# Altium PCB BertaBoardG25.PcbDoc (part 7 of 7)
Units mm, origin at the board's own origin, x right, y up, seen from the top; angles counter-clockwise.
Board outline 160 x 160 mm, 4 copper layers (Top, GND Plane, Power Plane, Bottom), stack 1.344 mm thick; 17 components, 112 nets, 2311 pads, 138 vias.
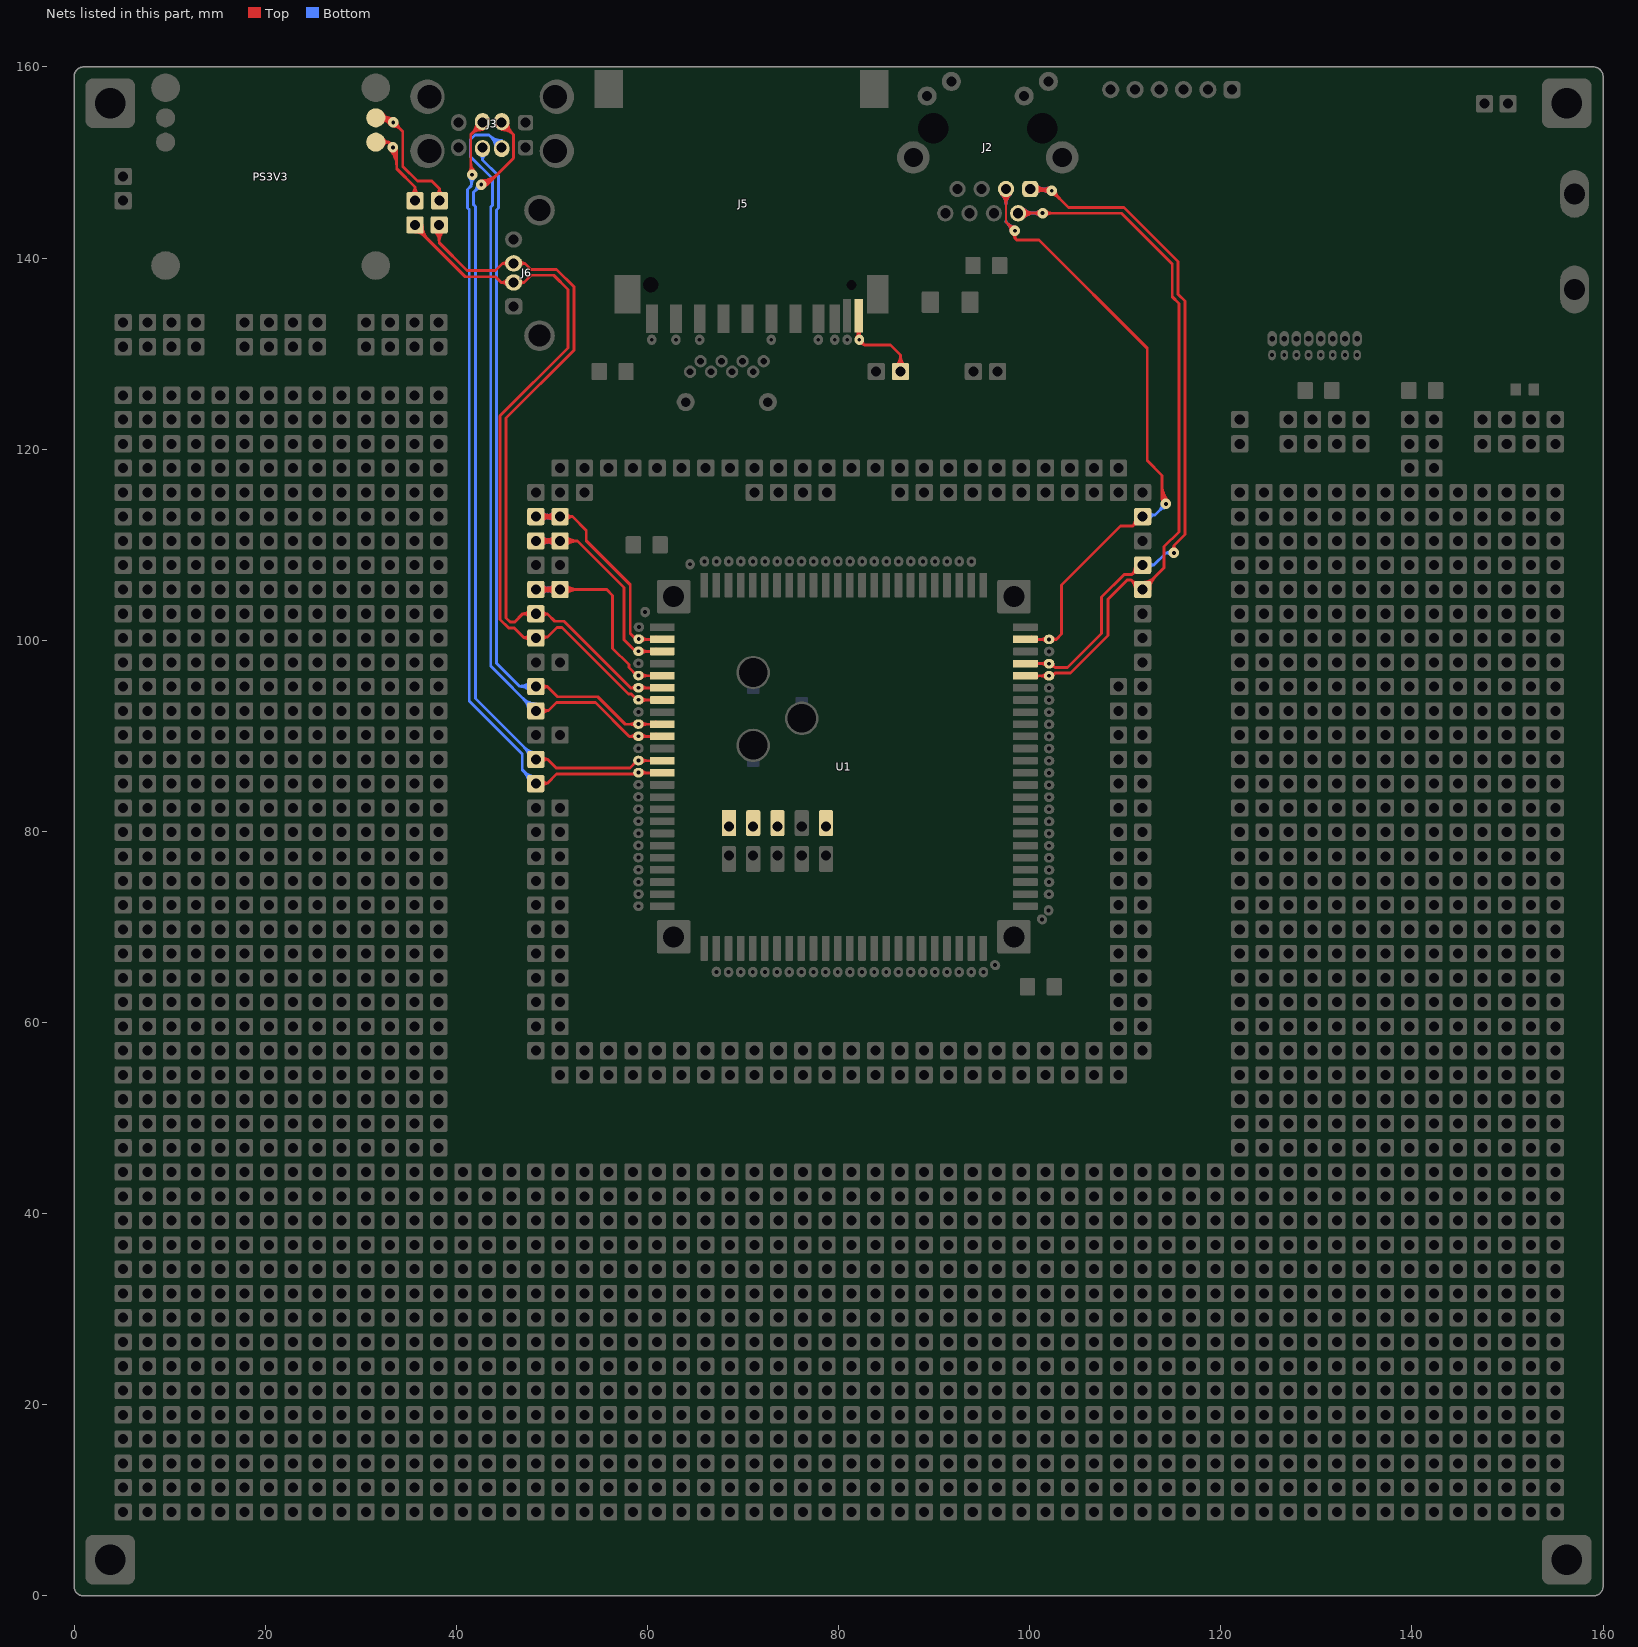
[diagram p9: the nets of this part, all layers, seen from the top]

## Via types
v1: diameter 1.5, hole 0.7, Top to Bottom, tented both sides, 54 vias
v2: diameter 1.1, hole 0.4, Top to Bottom, tented both sides, 49 vias
v3: diameter 1.9, hole 1.05, Top to Bottom, tented both sides, 17 vias
v4: diameter 1.9, hole 1.05, Top to Bottom, 16 vias
v5: diameter 0.9, hole 0.4, Top to Bottom, tented both sides, 2 vias

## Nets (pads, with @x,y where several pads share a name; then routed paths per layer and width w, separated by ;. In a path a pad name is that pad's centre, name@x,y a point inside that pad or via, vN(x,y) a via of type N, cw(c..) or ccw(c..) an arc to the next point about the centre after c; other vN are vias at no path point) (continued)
RX_P: J2.3 pad.0@102.032,100.097 pad.0@111.822,112.94 U1.W2 | length 95.5
  Top w0.25: J2.3@97.006,146.715 cw(c95.769,145.477) 97.519,145.477 cw(c99.269,145.477) J2.3@98.032,146.715 ; J2.3@97.183,146.892 cw(c96.372,146.081) 97.519,146.081 cw(c98.666,146.081) J2.3@97.855,146.892 ; 97.519,143.781 J2.3@97.519,147.228
  Top w0.3: 97.519,143.781 98.241,143.059 98.241,142.62 98.431,142.43 98.431,142.12 ; v2@98.051,142.85 ccw(c97.085,142.85) 97.768,143.533 ccw(c98.451,144.216) v2@98.451,143.25 ; v2@98.221,142.522 cw(c97.94,142.119) 98.431,142.119 ; v2@98.652,142.504 ccw(c98.877,142.119) 98.431,142.119 ; U1.W2@99.551,100.105 102.806,100.105 ; U1.W2@99.992,100.145 ccw(c100.089,100.243) U1.W2@100.089,100.105 ; U1.W2@100.204,100.357 ccw(c100.813,100.967) U1.W2@100.813,100.105 ; 101.119,100.105 cw(c101.119,99.234) pad.0@101.735,99.85 ; 101.155,100.105 ccw(c101.155,100.924) pad.0@101.735,100.345 ; pad.0@102.353,100.319 ccw(c102.806,100.691) 102.806,100.105 ; pad.0@102.36,99.885 cw(c102.806,99.543) 102.806,100.105 ; pad.0@111.078,112.841 cw(c110.033,112.703) 110.778,111.958 ; pad.0@111.653,112.209 ccw(c111.442,111.294) 110.778,111.958 ; pad.0@111.801,112.98 110.778,111.958 ; 113.861,114.751 ccw(c114.742,114.751) v2@114.119,114.128 ; 113.861,115.476 ccw(c115.466,115.476) v2@114.331,114.341 ; 113.861,116.2 ccw(c116.191,116.2) v2@114.543,114.553 ; v2@113.91,114.462 ccw(c113.66,114.598) 113.861,114.8 ; v2@114.061,114.3 114.061,114.6 113.861,114.8 ; v2@114.224,114.668 cw(c114.183,115.122) 113.861,114.8 ; 98.431,142.12 98.651,141.9 100.971,141.9 112.305,130.566 112.305,118.816 113.861,117.26 113.861,114.8 ; 102.806,100.105 103.347,100.645 103.347,105.785 109.519,111.958 110.778,111.958
  Bottom w0.25: J2.3@97.006,146.715 cw(c95.769,145.477) 97.519,145.477 cw(c99.269,145.477) J2.3@98.032,146.715 ; J2.3@97.183,146.892 cw(c96.372,146.081) 97.519,146.081 cw(c98.666,146.081) J2.3@97.855,146.892 ; 97.519,143.85 J2.3@97.519,147.228
  Bottom w0.3: 97.519,143.85 97.521,143.848 97.521,143.78 v2(98.451,142.85) ; v2@98.051,142.85 ccw(c97.085,142.85) 97.768,143.533 ccw(c98.451,144.216) v2@98.451,143.25 ; pad.0@111.811,112.99 111.691,113.11 113.101,113.11 ; pad.0@112.386,113.434 ccw(c113.101,114.061) 113.101,113.11 ; pad.0@112.533,112.701 cw(c113.101,112.51) 113.101,113.11 ; 113.577,113.586 ccw(c112.893,114.27) v2@113.861,114.27 ; 113.579,113.588 cw(c114.261,112.906) v2@114.261,113.87 ; v2@114.271,114.28 113.101,113.11
  other v2: 114.261,114.27
SHDN: pad.0@48.322,110.4 pad.0@50.862,110.4 pad.0@59.06,98.852 U1.E22 | length 57.7
  Top w0.3: pad.0@48.322,110.4 pad.0@50.862,110.4 52.69,110.4 57.561,105.529 57.561,100.06 58.786,98.835 U1.E22@61.551,98.835 ; pad.0@48.64,110.081 cw(c49.408,109.313) 49.408,110.4 cw(c49.408,111.486) pad.0@48.64,110.718 ; pad.0@48.852,109.869 cw(c50.132,108.589) 50.132,110.4 cw(c50.132,112.21) pad.0@48.852,110.93 ; 49.949,110.35 cw(c50.077,109.871) pad.0@50.488,110.148 ; 49.949,110.449 ccw(c50.077,110.928) pad.0@50.488,110.651 ; pad.0@50.204,110.039 ccw(c49.266,109.523) 49.543,110.558 ccw(c49.709,111.176) pad.0@50.24,110.818 ; pad.0@50.204,110.761 cw(c49.266,111.276) 49.543,110.242 cw(c49.709,109.623) pad.0@50.24,109.981 ; pad.0@50.331,109.869 ccw(c49.051,108.589) 49.051,110.4 ccw(c49.051,112.21) pad.0@50.331,110.93 ; pad.0@50.544,110.081 ccw(c49.775,109.313) 49.775,110.4 ccw(c49.775,111.486) pad.0@50.544,110.718 ; pad.0@51.18,110.081 cw(c51.948,109.313) 51.948,110.4 cw(c51.948,111.486) pad.0@51.18,110.718 ; pad.0@51.392,109.869 cw(c52.672,108.589) 52.672,110.4 cw(c52.672,112.21) pad.0@51.392,110.93 ; pad.0@59.357,98.605 cw(c59.913,98.049) 59.913,98.835 ; pad.0@59.357,99.1 ccw(c59.997,99.739) 59.997,98.835 ; U1.E22@60.289,98.835 ccw(c60.289,99.697) U1.E22@60.899,99.087 ; U1.E22@61.013,98.835 ccw(c61.013,98.973) U1.E22@61.111,98.875
  Bottom w0.3: pad.0@48.322,110.4 pad.0@50.862,110.4 ; pad.0@48.64,110.081 cw(c49.408,109.313) 49.408,110.4 cw(c49.408,111.486) pad.0@48.64,110.718 ; pad.0@48.852,109.869 cw(c50.132,108.589) 50.132,110.4 cw(c50.132,112.21) pad.0@48.852,110.93 ; 49.949,110.35 cw(c50.077,109.871) pad.0@50.488,110.148 ; 49.949,110.449 ccw(c50.077,110.928) pad.0@50.488,110.651 ; pad.0@50.204,110.039 ccw(c49.266,109.523) 49.543,110.558 ccw(c49.709,111.176) pad.0@50.24,110.818 ; pad.0@50.204,110.761 cw(c49.266,111.276) 49.543,110.242 cw(c49.709,109.623) pad.0@50.24,109.981 ; pad.0@50.331,109.869 ccw(c49.051,108.589) 49.051,110.4 ccw(c49.051,112.21) pad.0@50.331,110.93 ; pad.0@50.544,110.081 ccw(c49.775,109.313) 49.775,110.4 ccw(c49.775,111.486) pad.0@50.544,110.718
TCK: U1.1
TDI: U1.9
TDO: U1.3
TMS: U1.5
TX_N: J2.2 pad.0@102.032,96.287 pad.0@111.822,105.32 U1.W5 | length 98.8
  Top w0.3: J2.2@98.789,144.688 98.801,144.7 v2(101.351,144.7) ; J2.2@99.072,144.405 cw(c99.784,143.693) 99.784,144.7 ; J2.2@99.072,144.971 ccw(c99.726,145.624) 99.726,144.7 ; J2.2@99.284,144.193 cw(c100.508,142.968) 100.508,144.7 ; J2.2@99.284,145.183 ccw(c100.45,146.348) 100.45,144.7 ; U1.W5@99.551,96.295 99.559,96.287 pad.0@102.032,96.287 ; U1.W5@99.945,96.387 ccw(c100.154,96.555) U1.W5@100.154,96.287 ; U1.W5@100.191,96.453 ccw(c100.792,96.936) U1.W5@100.792,96.164 ; v2@101.068,144.417 ccw(c100.385,143.734) 100.385,144.7 ccw(c100.385,145.666) v2@101.068,144.983 ; v2@101.351,144.688 109.613,144.688 114.921,139.379 114.921,135.95 115.611,135.26 115.611,111.35 114.071,109.81 114.071,107.59 pad.0@111.831,105.35 ; v2@101.633,144.417 cw(c102.287,143.763) 102.287,144.688 ; v2@101.633,144.983 ccw(c102.346,145.695) 102.346,144.688 ; pad.0@101.735,96.04 ccw(c101.137,95.442) 101.137,96.287 ccw(c101.137,97.132) pad.0@101.735,96.535 ; pad.0@102.032,96.295 102.396,96.295 102.67,96.568 ; pad.0@102.309,96.554 ccw(c102.482,96.757) 102.67,96.568 ; 110.697,106.224 cw(c109.793,105.32) pad.0@111.072,105.32 ; pad.0@110.982,105.939 ccw(c111.499,106.456) pad.0@111.699,105.752 ; pad.0@111.617,106.041 cw(c111.339,107.018) 110.621,106.3 ; pad.0@111.822,105.77 ccw(c111.822,106.806) pad.0@112.555,106.073 ; pad.0@111.822,106.07 ccw(c111.822,107.83) 113.067,106.585 ; pad.0@111.831,105.34 111.581,105.34 110.621,106.3 ; pad.0@112.272,105.32 cw(c113.408,105.32) pad.0@112.605,106.123 ; pad.0@112.572,105.32 cw(c114.432,105.32) 113.117,106.635 ; 102.67,96.568 104.27,96.568 108.201,100.499 108.201,104.299 110.201,106.3 110.621,106.3
  Bottom w0.3: J2.2@98.801,144.7 v2(101.351,144.7) ; J2.2@99.072,144.405 cw(c99.784,143.693) 99.784,144.7 ; J2.2@99.072,144.971 ccw(c99.726,145.624) 99.726,144.7 ; J2.2@99.284,144.193 cw(c100.508,142.968) 100.508,144.7 ; J2.2@99.284,145.183 ccw(c100.45,146.348) 100.45,144.7 ; v2@101.068,144.417 ccw(c100.385,143.734) 100.385,144.7 ccw(c100.385,145.666) v2@101.068,144.983
TX_P: J2.1 pad.0@102.032,97.557 pad.0@111.822,107.86 U1.W4 | length 98.6
  Top w0.3: U1.W4@99.551,97.565 99.559,97.557 pad.0@102.032,97.557 ; U1.W4@99.945,97.657 ccw(c100.153,97.825) U1.W4@100.153,97.557 ; J2.1@100.237,147.05 v2(102.301,147.05) 104.051,145.3 109.881,145.3 115.525,139.656 115.525,136.216 116.241,135.5 116.241,111.057 115.091,109.907 ; J2.1@100.342,147.511 ccw(c101.454,148.623) 101.454,147.05 ; J2.1@100.554,146.733 cw(c101.32,145.967) 101.32,147.05 ; J2.1@100.554,147.723 ccw(c102.178,149.347) v2@102.178,147.05 ; 101.286,147.289 ccw(c101.564,148.326) v2@102.101,147.396 ; 101.433,147.25 cw(c101.211,146.421) v2@101.954,146.85 ; pad.0@101.735,97.31 ccw(c101.137,96.712) 101.137,97.557 ccw(c101.137,98.402) pad.0@101.735,97.805 ; v2@102.018,146.767 ccw(c101.335,146.084) 101.335,147.05 ccw(c101.335,148.016) v2@102.018,147.333 ; pad.0@102.032,97.565 102.256,97.565 102.661,97.16 ; pad.0@102.227,97.239 cw(c102.387,96.886) 102.661,97.16 ; v2@102.301,146.65 cw(c102.301,145.684) 102.983,146.367 cw(c103.666,147.05) v2@102.701,147.05 ; pad.0@102.432,97.557 ccw(c102.84,97.557) 102.552,97.269 ; pad.0@111.063,107.261 cw(c111.522,106.802) pad.0@111.699,107.427 ; pad.0@111.072,107.836 cw(c109.805,107.796) 110.701,106.9 ; pad.0@111.617,107.138 ccw(c111.362,106.239) 110.701,106.9 ; pad.0@111.901,107.88 111.681,107.88 110.701,106.9 ; v2@114.869,109.476 ccw(c114.562,109.907) 115.091,109.907 ; v2(115.101,109.15) 115.091,109.159 115.091,109.907 ; v2@115.32,109.485 cw(c115.596,109.907) 115.091,109.907 ; 102.661,97.16 103.961,97.16 107.521,100.719 107.521,104.519 109.901,106.9 110.701,106.9
  Bottom w0.3: J2.1@100.059,147.228 100.237,147.05 v2(102.301,147.05) ; J2.1@100.342,147.511 ccw(c101.454,148.623) 101.454,147.05 ; J2.1@100.554,146.733 cw(c101.32,145.967) 101.32,147.05 ; J2.1@100.554,147.723 ccw(c102.178,149.347) v2@102.178,147.05 ; 101.286,147.289 ccw(c101.564,148.326) v2@102.101,147.396 ; 101.433,147.25 cw(c101.211,146.421) v2@101.954,146.85 ; v2@102.018,146.767 ccw(c101.335,146.084) 101.335,147.05 ccw(c101.335,148.016) v2@102.018,147.333 ; pad.0@111.831,107.89 112.99,107.89 ; pad.0@112.492,108.197 ccw(c112.99,108.448) 112.99,107.89 ; pad.0@112.514,107.572 cw(c112.99,107.374) 112.99,107.89 ; v2@114.792,108.895 ccw(c114.251,108.447) 114.251,109.15 ; v2@114.792,109.405 cw(c114.251,109.853) 114.251,109.15 ; v2@114.901,109.15 114.251,109.15 ; 112.99,107.89 114.251,109.15
USBA_N: J6.2 pad.0@35.691,143.46 pad.0@48.322,100.24 pad.0@59.06,93.772 U1.E18 | length 90.2
  Top w0.3: pad.0@35.4,143.43 35.551,143.43 40.931,138.05 44.101,138.05 44.703,137.447 ; pad.0@35.691,142.71 cw(c35.691,141.31) 36.681,142.3 ; pad.0@36.141,143.46 ccw(c37.638,143.46) 36.58,142.401 ; pad.0@36.441,143.46 ccw(c38.662,143.46) 37.092,141.889 ; J6.2@45.428,137.072 ccw(c44.703,136.559) 44.703,137.447 ; J6.2@45.428,137.822 cw(c44.703,138.335) 44.703,137.447 ; J6.2@46.648,137.173 cw(c47.078,136.973) 47.078,137.447 ; J6.2@46.648,137.721 ccw(c47.078,137.921) 47.078,137.447 ; pad.0@47.646,99.915 ccw(c47.081,99.643) 47.081,100.27 ; pad.0@47.671,100.612 cw(c47.081,100.949) 47.081,100.27 ; pad.0@48.331,100.27 47.081,100.27 ; pad.0@48.331,100.34 49.541,100.34 ; pad.0@48.944,100.658 ccw(c49.541,101.058) 49.541,100.34 ; pad.0@49.026,99.981 cw(c49.541,99.791) 49.541,100.34 ; pad.0@59.357,93.525 cw(c59.913,92.969) 59.913,93.755 ; pad.0@59.357,94.02 ccw(c59.997,94.659) 59.997,93.755 ; U1.E18@60.305,93.755 ccw(c60.305,94.579) U1.E18@60.907,94.015 ; U1.E18@60.997,93.755 ccw(c60.997,93.931) U1.E18@61.126,93.81 ; U1.E18@61.551,93.755 58.921,93.755 58.306,94.37 58.027,94.37 51.061,101.336 50.537,101.336 49.541,100.34 ; 44.703,137.447 J6.2@46.009,137.447 47.078,137.447 ; 47.078,137.447 47.831,138.2 50.201,138.2 51.701,136.7 51.701,130.599 44.591,123.49 44.591,102.186 45.497,101.28 46.071,101.28 47.081,100.27
USBA_N_2: pad.0@35.691,146 PS3V3.6 | length 16.7
  Top w0.3: PS3V3.6@31.579,152.132 32.919,152.132 ; PS3V3.6@32.348,151.77 cw(c32.918,151.501) 32.918,152.132 ; PS3V3.6@32.348,152.494 ccw(c32.918,152.762) 32.918,152.132 ; v2@33.001,151.721 ccw(c32.651,151.865) 32.919,152.132 ; v2@33.088,151.287 cw(c31.44,149.638) 33.771,149.638 ; v2@33.3,151.499 cw(c32.164,150.363) 33.771,150.363 ; v2@33.347,151.969 cw(c33.314,152.527) 32.919,152.132 ; v2@33.513,151.711 cw(c32.888,151.087) 33.771,151.087 ; pad.0@35.265,146.617 ccw(c34.703,147.43) 35.691,147.43 ; pad.0@35.691,145.97 pad.0@35.691,146 35.691,147.43 ; pad.0@36.118,146.617 cw(c36.679,147.43) 35.691,147.43 ; 32.919,152.132 33.771,151.279 33.771,149.35 35.691,147.43
  other v2: 33.371,151.57
USBA_P: J6.3 pad.0@38.211,143.46 pad.0@48.322,102.78 pad.0@59.06,95.042 U1.E19 | length 89.8
  Top w0.3: pad.0@37.681,142.929 cw(c36.4,141.649) 38.211,141.649 cw(c40.022,141.649) pad.0@38.741,142.929 ; pad.0@37.893,143.142 cw(c37.125,142.373) 38.211,142.373 cw(c39.298,142.373) pad.0@38.529,143.142 ; pad.0@38.211,143.41 38.211,141.61 41.121,138.7 44.101,138.7 44.848,139.447 ; J6.3@45.392,139.128 ccw(c44.848,138.822) 44.848,139.447 ; J6.3@45.392,139.766 cw(c44.848,140.072) 44.848,139.447 ; J6.3@46.622,139.122 cw(c47.184,138.799) 47.184,139.447 ; J6.3@46.622,139.772 ccw(c47.184,140.095) 47.184,139.447 ; pad.0@47.688,102.379 ccw(c46.961,101.92) 46.961,102.78 ; pad.0@47.688,103.18 cw(c46.961,103.639) 46.961,102.78 ; pad.0@48.201,102.74 49.561,102.74 ; pad.0@48.322,102.78 46.961,102.78 ; pad.0@48.969,102.401 cw(c49.561,102.054) 49.561,102.74 ; pad.0@49.002,103.096 ccw(c49.561,103.356) 49.561,102.74 ; pad.0@58.733,95.256 cw(c58.261,95.622) 58.261,95.025 ; pad.0@58.75,94.807 ccw(c58.261,94.365) 58.261,95.025 ; pad.0@59.357,94.795 cw(c59.913,94.239) 59.913,95.025 ; pad.0@59.357,95.29 ccw(c59.997,95.929) 59.997,95.025 ; U1.E19@60.289,95.025 ccw(c60.289,95.887) U1.E19@60.899,95.277 ; U1.E19@61.013,95.025 ccw(c61.013,95.163) U1.E19@61.111,95.065 ; U1.E19@61.551,95.025 58.261,95.025 ; 44.848,139.447 J6.3@46.009,139.447 47.184,139.447 ; 46.961,102.78 46.081,101.9 45.661,101.9 45.215,102.345 45.215,123.264 52.301,130.35 52.301,136.999 50.501,138.8 47.831,138.8 47.184,139.447 ; 49.561,102.74 50.301,102 51.286,102 58.261,95.025
USBA_P_2: pad.0@38.241,146 PS3V3.7 | length 24
  Top w0.3: PS3V3.7@32.204,154.672 cw(c32.204,153.232) v2@33.328,154.132 ; PS3V3.7@32.333,154.28 cw(c32.978,153.945) 32.978,154.672 ; PS3V3.7@32.333,155.064 ccw(c32.978,155.399) 32.978,154.672 ; 32.616,154.769 cw(c32.345,153.757) v2@33.313,154.157 ; 32.829,154.672 cw(c32.829,153.733) v2@33.562,154.32 ; 32.834,154.711 cw(c32.666,154.085) v2@33.307,154.18 ; v2@33.039,154.354 ccw(c32.776,154.469) 32.979,154.672 ; v2@33.093,153.945 ccw(c31.579,152.731) PS3V3.7@31.579,154.672 32.979,154.672 ; v2@33.306,154.582 cw(c33.221,154.914) 32.979,154.672 ; v2@33.406,153.795 cw(c33.406,152.708) 34.174,153.477 ; v2@33.806,154.195 ccw(c34.651,154.195) 34.053,153.597 ; pad.0@37.888,146.661 ccw(c37.574,147.25) 38.241,147.25 ; pad.0@38.241,145.979 pad.0@38.241,146 38.241,147.25 ; pad.0@38.594,146.661 cw(c38.908,147.25) 38.241,147.25 ; 32.979,154.672 34.401,153.25 34.401,149.58 35.931,148.05 37.441,148.05 38.241,147.25
  other v2: 33.406,154.195
USBB_N: J3.2 pad.0@48.322,92.62 pad.0@59.06,89.962 U1.E15 | length 94.7
  Top w0.3: pad.0@48.331,92.64 49.641,92.64 ; pad.0@48.957,93.018 ccw(c49.641,93.446) 49.641,92.64 ; pad.0@48.975,92.251 cw(c49.641,91.876) 49.641,92.64 ; 58.123,89.945 ccw(c58.123,90.849) pad.0@58.762,90.21 ; 58.207,89.945 cw(c58.207,89.159) pad.0@58.762,89.715 ; pad.0@59.357,89.715 cw(c59.913,89.159) 59.913,89.945 ; pad.0@59.357,90.21 ccw(c59.997,90.849) 59.997,89.945 ; U1.E15@60.289,89.945 ccw(c60.289,90.807) U1.E15@60.899,90.197 ; U1.E15@61.013,89.945 ccw(c61.013,90.083) U1.E15@61.111,89.985 ; U1.E15@61.551,89.945 58.108,89.945 54.553,93.5 50.501,93.5 49.641,92.64
  Bottom w0.3: 43.472,152.833 ccw(c44.752,154.113) J3.2@44.752,152.303 ; 43.713,152.592 cw(c42.774,151.653) J3.2@44.102,151.653 ; 43.984,152.321 ccw(c44.752,153.089) J3.2@44.752,152.003 ; J3.2@44.752,151.553 43.439,152.866 43.046,152.866 41.967,152.866 41.501,152.4 41.501,150.6 43.775,148.325 43.775,145.528 43.601,145.353 43.601,97.3 48.251,92.65 pad.0@48.331,92.65 ; 46.972,93.929 ccw(c48.322,95.279) pad.0@48.322,93.37 ; 47.07,93.83 cw(c45.86,92.62) pad.0@47.572,92.62 ; pad.0@47.484,93.417 ccw(c48.322,94.255) pad.0@48.322,93.07 ; pad.0@47.582,93.318 cw(c46.884,92.62) pad.0@47.872,92.62
USBB_P: J3.3 pad.0@48.322,95.16 pad.0@59.06,91.232 U1.E16 | length 85.1
  Top w0.3: pad.0@48.401,95.15 49.551,95.15 ; pad.0@48.985,94.809 cw(c49.551,94.51) 49.551,95.15 ; pad.0@48.993,95.495 ccw(c49.551,95.773) 49.551,95.15 ; 58.123,91.215 ccw(c58.123,92.119) pad.0@58.762,91.48 ; 58.207,91.215 cw(c58.207,90.429) pad.0@58.762,90.985 ; pad.0@59.357,90.985 cw(c59.913,90.429) 59.913,91.215 ; pad.0@59.357,91.48 ccw(c59.997,92.119) 59.997,91.215 ; U1.E16@60.289,91.215 ccw(c60.289,92.077) U1.E16@60.899,91.467 ; U1.E16@61.013,91.215 ccw(c61.013,91.353) U1.E16@61.111,91.255 ; U1.E16@61.551,91.215 57.68,91.215 54.795,94.1 50.601,94.1 49.551,95.15
  Bottom w0.3: J3.3@42.403,150.904 cw(c41.999,150.269) 42.752,150.269 ; J3.3@42.752,151.553 42.752,150.269 ; J3.3@43.101,150.904 ccw(c43.505,150.269) 42.752,150.269 ; 47.269,95.19 cw(c47.269,94.245) pad.0@47.982,94.864 ; 47.324,95.19 ccw(c47.324,96.136) pad.0@48,95.474 ; pad.0@47.755,94.668 ccw(c46.611,93.673) 46.611,95.19 ; pad.0@47.786,95.684 cw(c46.611,96.833) 46.611,95.19 ; pad.0@48.331,95.19 46.611,95.19 ; 42.752,150.269 44.41,148.611 44.41,145.248 44.201,145.039 44.201,97.6 46.611,95.19
USBC_N: J3.6 pad.0@48.322,87.54 pad.0@59.06,87.422 U1.E13 | length 101.7
  Top w0.3: v2@42.606,147.495 ccw(c42.606,148.535) 43.341,147.799 ; v2(42.606,147.695) 43.236,147.695 ; v2@42.606,147.795 ccw(c42.606,149.559) 43.853,148.312 ; v2@42.606,148.095 ccw(c42.606,150.583) 44.365,148.824 ; v2@42.967,147.524 cw(c43.236,147.398) 43.236,147.695 ; v2@42.967,147.865 ccw(c43.236,147.992) 43.236,147.695 ; J3.6@44.752,154.173 45.992,152.933 ; J3.6@44.76,153.723 cw(c44.785,152.716) 45.497,153.428 ; J3.6@44.768,153.423 cw(c44.808,151.748) 45.992,152.933 ; J3.6@45.402,154.073 ccw(c46.73,154.073) 45.791,153.134 ; pad.0@48.331,87.56 49.541,87.56 ; pad.0@48.983,87.894 ccw(c49.541,88.193) 49.541,87.56 ; pad.0@48.999,87.218 cw(c49.541,86.96) 49.541,87.56 ; pad.0@59.357,87.175 cw(c59.913,86.619) 59.913,87.405 ; pad.0@59.357,87.67 ccw(c59.997,88.309) 59.997,87.405 ; U1.E13@60.306,87.405 ccw(c60.306,88.226) U1.E13@60.907,87.666 ; U1.E13@60.996,87.405 ccw(c60.996,87.583) U1.E13@61.127,87.461 ; U1.E13@61.551,87.405 58.926,87.405 58.161,86.64 50.461,86.64 49.541,87.56 ; 43.236,147.695 45.992,150.451 45.992,152.933
  Bottom w0.3: v2@42.206,147.695 cw(c41.24,147.695) 41.923,147.012 cw(c42.606,146.329) v2@42.606,147.295 ; v2(42.606,147.695) 41.819,146.909 41.819,145.579 42.001,145.397 42.001,93.9 pad.0@48.331,87.57 ; 47.13,88.782 cw(c45.782,87.434) pad.0@47.688,87.434 ; 47.156,88.745 ccw(c48.368,89.958) pad.0@48.368,88.243
USBC_P: J3.7 pad.0@48.322,85 pad.0@59.06,86.152 U1.E12 | length 101.1
  Top w0.3: v2@41.363,149.008 ccw(c41.002,149.368) 41.512,149.368 ; 41.512,149.288 ccw(c42.209,149.288) v2@41.716,148.796 ; 41.512,150.013 ccw(c42.933,150.013) v2@41.928,149.008 ; v2(41.646,148.725) 41.512,148.858 41.512,152.933 ; 41.713,153.134 ccw(c40.774,154.073) J3.7@42.102,154.073 ; 42.008,153.428 cw(c42.72,152.716) J3.7@42.744,153.723 ; J3.7@42.737,153.423 ccw(c42.697,151.748) 41.512,152.933 ; J3.7@42.752,154.173 41.512,152.933 ; pad.0@48.331,85.04 49.541,85.04 ; pad.0@48.974,85.37 ccw(c49.541,85.691) 49.541,85.04 ; pad.0@49.006,84.694 cw(c49.541,84.455) 49.541,85.04 ; pad.0@59.357,85.905 cw(c59.913,85.349) 59.913,86.135 ; pad.0@59.357,86.4 ccw(c59.997,87.039) 59.997,86.135 ; U1.E12@60.889,86.135 ccw(c60.889,86.521) U1.E12@61.238,86.355 ; U1.E12@61.364,86.135 ccw(c61.364,86.294) U1.E12@61.509,86.226 ; U1.E12@61.551,86.135 59.462,86.135 59.327,86 50.501,86 49.541,85.04
  Bottom w0.3: v2@41.363,148.442 cw(c40.874,147.953) 41.565,147.953 ; 41.565,147.565 cw(c42.805,147.565) v2@41.928,148.442 ; v2@41.641,148.68 41.565,148.604 41.565,147.56 41.184,147.179 41.184,145.248 41.362,145.071 41.362,93.65 46.901,88.111 46.901,86.46 pad.0@48.331,85.03 ; 47.013,86.347 cw(c45.666,85) pad.0@47.572,85 ; 47.109,86.252 ccw(c48.322,87.465) pad.0@48.322,85.75 ; pad.0@47.526,85.835 cw(c46.69,85) pad.0@47.872,85 ; pad.0@47.621,85.74 ccw(c48.322,86.44) pad.0@48.322,85.45
VBAT: pad.0@48.322,105.32 pad.0@50.862,105.32 pad.0@59.06,96.312 U1.E20 | length 56.9
  Top w0.3: pad.0@48.322,105.32 55.738,105.32 56.361,104.697 56.361,99.16 58.061,97.46 58.061,97.16 58.926,96.295 U1.E20@61.551,96.295 ; pad.0@48.64,105.001 cw(c49.408,104.233) 49.408,105.32 cw(c49.408,106.406) pad.0@48.64,105.638 ; pad.0@48.852,104.789 cw(c50.132,103.509) 50.132,105.32 cw(c50.132,107.13) pad.0@48.852,105.85 ; 49.949,105.27 cw(c50.077,104.791) pad.0@50.488,105.068 ; 49.949,105.369 ccw(c50.077,105.848) pad.0@50.488,105.571 ; pad.0@50.204,104.959 ccw(c49.266,104.443) 49.543,105.478 ccw(c49.709,106.096) pad.0@50.24,105.738 ; pad.0@50.204,105.681 cw(c49.266,106.196) 49.543,105.162 cw(c49.709,104.543) pad.0@50.24,104.901 ; pad.0@50.331,104.789 ccw(c49.051,103.509) 49.051,105.32 ccw(c49.051,107.13) pad.0@50.331,105.85 ; pad.0@50.544,105.001 ccw(c49.775,104.233) 49.775,105.32 ccw(c49.775,106.406) pad.0@50.544,105.638 ; pad.0@51.18,105.001 cw(c51.948,104.233) 51.948,105.32 cw(c51.948,106.406) pad.0@51.18,105.638 ; pad.0@51.392,104.789 cw(c52.672,103.509) 52.672,105.32 cw(c52.672,107.13) pad.0@51.392,105.85 ; pad.0@59.357,96.065 cw(c59.913,95.509) 59.913,96.295 ; pad.0@59.357,96.56 ccw(c59.997,97.199) 59.997,96.295 ; U1.E20@60.306,96.295 ccw(c60.306,97.116) U1.E20@60.907,96.556 ; U1.E20@60.996,96.295 ccw(c60.996,96.473) U1.E20@61.127,96.351
  Bottom w0.3: pad.0@48.322,105.32 pad.0@50.862,105.32 ; pad.0@48.64,105.001 cw(c49.408,104.233) 49.408,105.32 cw(c49.408,106.406) pad.0@48.64,105.638 ; pad.0@48.852,104.789 cw(c50.132,103.509) 50.132,105.32 cw(c50.132,107.13) pad.0@48.852,105.85 ; 49.949,105.27 cw(c50.077,104.791) pad.0@50.488,105.068 ; 49.949,105.369 ccw(c50.077,105.848) pad.0@50.488,105.571 ; pad.0@50.204,104.959 ccw(c49.266,104.443) 49.543,105.478 ccw(c49.709,106.096) pad.0@50.24,105.738 ; pad.0@50.204,105.681 cw(c49.266,106.196) 49.543,105.162 cw(c49.709,104.543) pad.0@50.24,104.901 ; pad.0@50.331,104.789 ccw(c49.051,103.509) 49.051,105.32 ccw(c49.051,107.13) pad.0@50.331,105.85 ; pad.0@50.544,105.001 ccw(c49.775,104.233) 49.775,105.32 ccw(c49.775,106.406) pad.0@50.544,105.638
WKUP: pad.0@48.322,112.94 pad.0@50.862,112.94 pad.0@59.085,100.122 U1.E23 | length 55.7
  Top w0.3: pad.0@48.322,112.94 pad.0@50.862,112.94 52.161,112.94 ; pad.0@48.64,112.621 cw(c49.408,111.853) 49.408,112.94 cw(c49.408,114.026) pad.0@48.64,113.258 ; pad.0@48.852,112.409 cw(c50.132,111.129) 50.132,112.94 cw(c50.132,114.75) pad.0@48.852,113.47 ; 49.949,112.89 cw(c50.077,112.411) pad.0@50.488,112.688 ; 49.949,112.989 ccw(c50.077,113.468) pad.0@50.488,113.191 ; pad.0@50.204,112.579 ccw(c49.266,112.063) 49.543,113.098 ccw(c49.709,113.716) pad.0@50.24,113.358 ; pad.0@50.204,113.301 cw(c49.266,113.816) 49.543,112.782 cw(c49.709,112.163) pad.0@50.24,112.521 ; pad.0@50.331,112.409 ccw(c49.051,111.129) 49.051,112.94 ccw(c49.051,114.75) pad.0@50.331,113.47 ; pad.0@50.544,112.621 ccw(c49.775,111.853) 49.775,112.94 ccw(c49.775,114.026) pad.0@50.544,113.258 ; pad.0@51.511,112.565 cw(c52.161,112.189) 52.161,112.94 ; pad.0@51.511,113.315 ccw(c52.161,113.69) 52.161,112.94 ; pad.0@59.383,99.875 cw(c59.938,99.319) 59.938,100.105 ; pad.0@59.383,100.37 ccw(c60.022,101.009) 60.022,100.105 ; U1.E23@60.289,100.105 ccw(c60.289,100.967) U1.E23@60.899,100.357 ; U1.E23@61.013,100.105 ccw(c61.013,100.243) U1.E23@61.111,100.145 ; U1.E23@61.551,100.105 58.816,100.105 58.201,100.72 58.201,105.81 53.601,110.41 53.601,111.5 52.161,112.94
  Bottom w0.3: pad.0@48.322,112.94 pad.0@50.862,112.94 ; pad.0@48.64,112.621 cw(c49.408,111.853) 49.408,112.94 cw(c49.408,114.026) pad.0@48.64,113.258 ; pad.0@48.852,112.409 cw(c50.132,111.129) 50.132,112.94 cw(c50.132,114.75) pad.0@48.852,113.47 ; 49.949,112.89 cw(c50.077,112.411) pad.0@50.488,112.688 ; 49.949,112.989 ccw(c50.077,113.468) pad.0@50.488,113.191 ; pad.0@50.204,112.579 ccw(c49.266,112.063) 49.543,113.098 ccw(c49.709,113.716) pad.0@50.24,113.358 ; pad.0@50.204,113.301 cw(c49.266,113.816) 49.543,112.782 cw(c49.709,112.163) pad.0@50.24,112.521 ; pad.0@50.331,112.409 ccw(c49.051,111.129) 49.051,112.94 ccw(c49.051,114.75) pad.0@50.331,113.47 ; pad.0@50.544,112.621 ccw(c49.775,111.853) 49.775,112.94 ccw(c49.775,114.026) pad.0@50.544,113.258
WP: J5.WP pad.0@82.174,131.451 pad.0@86.482,128.12 | length 18.5
  Top w0.3: pad.0@81.876,131.748 ccw(c81.33,132.294) J5.WP@82.102,132.294 ; J5.WP@81.89,132.441 cw(c81.378,131.928) 82.102,131.928 cw(c82.826,131.928) J5.WP@82.314,132.441 ; J5.WP@81.921,132.414 cw(c81.719,132.15) 82.04,132.064 ; J5.WP@81.952,132.393 cw(c81.703,131.961) 82.185,132.09 ; 82.062,132.145 cw(c82.456,132.04) J5.WP@82.252,132.393 ; J5.WP@82.102,132.398 ccw(c83.02,132.398) pad.0@82.371,131.748 ; J5.WP@82.102,133.953 82.102,131.499 82.701,130.9 ; pad.0@82.189,131.057 cw(c82.297,130.496) 82.701,130.9 ; 82.196,132.049 cw(c82.569,132.149) J5.WP@82.306,132.433 ; pad.0@82.474,131.401 ccw(c83.134,131.401) 82.667,130.934 ; pad.0@85.971,128.669 ccw(c84.886,129.839) 86.482,129.839 ; pad.0@86.176,128.449 ccw(c85.524,129.151) 86.482,129.151 ccw(c87.439,129.151) pad.0@86.788,128.449 ; pad.0@86.482,128.12 86.482,129.839 ; pad.0@86.992,128.669 cw(c88.078,129.839) 86.482,129.839 ; 82.701,130.9 85.421,130.9 86.482,129.839
pads on no net: J1.2 J1.5 J2.MH3 J2.MH4 J5.1@81.352,137.203 J5.2@60.352,137.203
copper on no net: | length 0.4
  Top w0.7: 4.91,14.05 5.041,13.919 ; 4.939,11.5 5.07,11.369

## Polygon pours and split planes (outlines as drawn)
no net on Top Solder "Top Solder-No Net" (solid): 34.951,143.079 34.901,143.129 34.901,146.479 36.351,146.479 36.351,143.029
no net on Top Solder "Top Solder-No Net" (solid): 37.641,142.989 37.591,143.039 37.591,146.389 39.041,146.389 39.041,142.939
no net on Top Solder "Top Solder-No Net" (solid): 150.502,155.459 150.452,155.409 147.102,155.409 147.102,156.859 150.552,156.859
GND on Top "Top-GND" (solid, remove dead copper, pour order 13): 1.919,149.56 2.123,149.369 158,149.369 158,3.843 1.918,3.843
GND on Top "Top-No Net" (solid, pour order 17): 158.001,148.99 158.001,159.16 105.851,159.16 105.851,148.99
GND on Top "Top-No Net" (solid, remove dead copper, pour order 15): 1.918,149.56 1.918,159.06 33.961,159.06 33.663,158.76 33.663,148.46
GND on Bottom "Bot-GND2" (solid, remove dead copper, pour order 11): 3.563,149.56 3.765,149.369 158,149.369 158,3.843 3.562,3.843
GND on Bottom "Bot-GND1" (solid, remove dead copper, pour order 14): 3.567,149.462 3.567,158.962 35.767,158.962 35.467,158.662 35.467,148.362
GND on Bottom "Bot-GND3" (solid, pour order 16): 158.001,146.508 158.001,159.16 105.851,159.16 105.851,146.508
GND on Bottom "Bot-GND2" (solid, pour order 12): 120.651,119.21 125.811,119.21 125.811,124.39 125.691,124.51 125.641,124.46 123.251,124.46 123.251,122.03 123.081,121.86 120.391,121.86 120.381,121.85
EARTH on GND Plane (split plane): 105.859,149.568 105.053,148.762 100.886,148.762 99.733,149.915 99.657,149.977 99.57,150.024 99.476,150.052 99.378,150.062 90.861,150.062 90.763,150.052 90.669,150.024 90.582,149.977 90.506,149.915 88.506,147.915 88.443,147.839 88.397,147.752 88.368,147.658 88.359,147.56 88.368,147.462 88.397,147.367 88.443,147.281 88.459,147.262 88.459,134.021 87.862,133.424 82.407,133.424 76.616,139.215 76.54,139.277 76.453,139.324 76.359,139.352 76.261,139.362 65.261,139.362 65.163,139.352 65.069,139.324 64.982,139.277 64.906,139.215 59.453,133.762 54.76,133.762 54.662,133.752 54.568,133.724 54.481,133.677 54.405,133.615 50.207,129.417 47.567,129.417 46.303,130.682 46.303,132.876 48.116,134.689 48.179,134.766 48.225,134.852 48.254,134.947 48.264,135.045 48.264,142.952 48.254,143.05 48.225,143.144 48.179,143.231 48.116,143.307 46.464,144.96 46.464,154.721 46.454,154.819 46.425,154.913 46.379,155 46.316,155.076 44.977,156.415 44.901,156.477 44.814,156.524 44.72,156.552 44.622,156.562 39.361,156.562 39.263,156.552 39.169,156.524 39.082,156.477 39.006,156.415 37.053,154.462 35.729,154.462 34.679,155.512 34.679,159.49 105.859,159.49
GND on GND Plane (split plane): 159.087,159.482 159.181,159.454 159.268,159.407 159.344,159.344 159.407,159.268 159.454,159.181 159.482,159.087 159.491,158.995 159.49,158.977 159.49,1 159.49,0.994 159.482,0.913 159.454,0.819 159.407,0.732 159.344,0.656 159.268,0.593 159.181,0.546 159.087,0.518 158.995,0.509 158.977,0.51 1,0.51 0.994,0.51 0.913,0.518 0.819,0.546 0.732,0.593 0.656,0.656 0.593,0.732 0.546,0.819 0.518,0.913 0.509,1.005 0.51,1.023 0.51,158.99 0.511,159 0.511,159.006 0.519,159.087 0.547,159.181 0.594,159.268 0.657,159.344 0.733,159.407 0.82,159.454 0.914,159.482 0.994,159.49 1,159.49 1.024,159.49 33.674,159.49 33.674,155.304 33.683,155.206 33.712,155.112 33.758,155.025 33.821,154.949 35.165,153.604 35.242,153.542 35.328,153.496 35.423,153.467 35.521,153.457 37.261,153.457 37.359,153.467 37.453,153.496 37.54,153.542 37.616,153.604 39.569,155.557 44.414,155.557 45.459,154.513 45.459,144.752 45.468,144.654 45.497,144.559 45.543,144.473 45.606,144.396 47.259,142.744 47.259,135.253 45.445,133.439 45.382,133.363 45.336,133.276 45.307,133.182 45.298,133.084 45.298,130.474 45.307,130.376 45.336,130.281 45.382,130.195 45.445,130.118 47.004,128.559 47.08,128.497 47.167,128.451 47.261,128.422 47.359,128.412 50.415,128.412 50.513,128.422 50.607,128.451 50.694,128.497 50.77,128.559 54.968,132.757 59.661,132.757 59.759,132.767 59.853,132.796 59.94,132.842 60.016,132.904 65.469,138.357 76.053,138.357 81.844,132.566 81.92,132.504 82.007,132.458 82.101,132.429 82.199,132.419 88.07,132.419 88.168,132.429 88.262,132.458 88.349,132.504 88.425,132.566 89.316,133.457 89.379,133.534 89.425,133.62 89.454,133.715 89.464,133.813 89.464,147.452 91.069,149.057 99.17,149.057 100.323,147.904 100.399,147.842 100.486,147.796 100.58,147.767 100.678,147.757 105.261,147.757 105.359,147.767 105.453,147.796 105.54,147.842 105.616,147.904 106.716,149.004 106.779,149.081 106.825,149.167 106.854,149.262 106.864,149.36 106.864,159.49 159,159.49 159.006,159.49
DIBN on Power Plane (split plane): 100.849,120.334 100.849,119.102 100.689,118.942 100.665,118.91 100.659,118.895 100.65,118.874 100.645,118.835 100.645,114.725 100.65,114.686 100.659,114.664 100.665,114.649 100.689,114.618 100.849,114.457 100.849,113.195 100.659,113.004 100.276,113.004 100.003,113.277 100.003,114.488 100.158,114.643 100.182,114.674 100.197,114.711 100.202,114.75 100.202,118.81 100.197,118.849 100.182,118.885 100.158,118.917 100.003,119.072 100.003,120.353 100.174,120.525 100.659,120.525
DIBP on Power Plane (split plane): 103.389,120.334 103.389,119.102 103.229,118.942 103.205,118.91 103.199,118.895 103.19,118.874 103.185,118.835 103.185,114.725 103.19,114.686 103.199,114.664 103.205,114.649 103.229,114.618 103.389,114.457 103.389,113.195 103.199,113.004 102.816,113.004 102.543,113.277 102.543,114.488 102.698,114.643 102.722,114.674 102.737,114.711 102.742,114.75 102.742,118.81 102.737,118.849 102.722,118.885 102.698,118.917 102.543,119.072 102.543,120.353 102.714,120.525 103.199,120.525
5V0 on Power Plane (split plane): 48.76,149.37 48.765,149.331 48.78,149.294 48.804,149.263 52.66,145.407 52.66,133.777 51.085,133.221 44.111,133.221 44.092,133.218 44.073,133.216 41.283,132.483 41.246,132.468 41.215,132.445 41.205,132.432 41.193,132.423 40.708,131.938 40.684,131.906 40.669,131.87 40.664,131.831 40.664,130.672 39.222,129.231 29.548,129.231 29.076,129.703 29.076,134.837 29.074,134.851 29.073,134.865 29.072,134.871 29.071,134.876 29.066,134.889 29.061,134.903 29.058,134.907 29.056,134.913 29.047,134.924 29.04,134.936 25.962,138.526 25.962,142.505 28.272,144.718 32.729,144.718 34.785,141.587 34.795,141.575 34.804,141.563 34.808,141.56 34.81,141.557 34.823,141.548 34.835,141.539 34.84,141.537 34.843,141.535 34.858,141.53 34.872,141.524 34.876,141.523 34.88,141.522 34.896,141.52 34.911,141.518 40.511,141.518 40.527,141.52 40.542,141.522 40.546,141.523 40.55,141.524 40.565,141.53 40.58,141.535 40.583,141.537 40.587,141.539 40.599,141.548 40.612,141.557 40.615,141.56 40.618,141.563 40.628,141.575 40.638,141.587 45.338,148.787 45.34,148.791 45.342,148.794 45.348,148.809 45.355,148.823 45.356,148.827 45.357,148.831 45.359,148.846 45.362,148.861 45.362,148.866 45.362,148.87 45.362,156.018 48.76,156.018
3V3 on Power Plane (split plane): 159.087,159.482 159.181,159.454 159.268,159.407 159.344,159.344 159.407,159.268 159.454,159.181 159.482,159.087 159.491,158.995 159.49,158.977 159.49,1 159.49,0.994 159.482,0.913 159.454,0.819 159.407,0.732 159.344,0.656 159.268,0.593 159.181,0.546 159.087,0.518 158.995,0.509 158.977,0.51 1,0.51 0.994,0.51 0.913,0.518 0.819,0.546 0.732,0.593 0.656,0.656 0.593,0.732 0.546,0.819 0.518,0.913 0.509,1.005 0.51,1.023 0.51,158.99 0.511,159 0.511,159.006 0.519,159.087 0.547,159.181 0.594,159.268 0.657,159.344 0.733,159.407 0.82,159.454 0.914,159.482 0.994,159.49 1,159.49 1.024,159.49 159,159.49 159.006,159.49

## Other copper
Top:
  pour cut-out: 62.551,102.557 62.548,102.554 62.548,101.964 60.643,101.964 60.541,102.066 60.541,103.006
  pour cut-out: 64.764,104.77 63.226,106.308 62.954,106.308 62.954,106.714 63.767,107.527 64.072,107.222 64.555,107.222 65.342,106.435 65.342,104.816 65.296,104.77
  pour cut-out: 96.339,68.77 96.336,68.767 95.898,68.767 95.737,68.928 95.476,68.928 95.476,67.131 95.924,66.684 96.482,66.684 96.482,66.811 96.66,66.989
  pour cut-out: 98.387,71.967 98.387,71.484 98.565,71.307 98.551,71.293 98.551,70.982 99.906,70.982 100.14,70.748 100.597,70.748 100.597,71.459 100.445,71.611 98.794,71.611 98.794,71.738 98.54,71.992
  pour cut-out: 62.612,72.365 61.041,72.365 60.77,72.094 60.77,70.392 61.961,70.392 62.551,70.982
  pour cut-out: 64.764,68.77 65.686,68.77 65.746,68.83 66.146,68.83 66.146,67.005 66.129,66.989 66.079,67.039 64.428,67.039
  pour cut-out: 95.543,106.079 95.543,104.708 95.605,104.77 96.339,104.77 96.339,106.571 96.355,106.587 96.305,106.638 95.593,106.638
  pour cut-out: 100.343,102.803 100.292,102.752 100.292,100.999 98.591,100.999 98.489,101.101 98.489,102.495 98.551,102.557
  pour cut-out: 107.69,115.885 109.079,115.913 109.079,116.857 109.002,117.512 108.952,117.588 107.766,117.625
  pour cut-out: 49.113,57.263 50.173,57.263 50.173,58.783 50.253,58.863 50.143,58.973 48.903,58.973
  pour cut-out: 51.065,56.32 51.065,55.26 52.585,55.26 52.665,55.18 52.775,55.29 52.775,56.53
  pour cut-out: 67.431,82.595 67.433,82.593 79.802,82.593 79.802,75.36 67.434,75.354
  pour cut-out: 120.409,116.88 158.014,116.88 158.014,1.308 127.319,1.308 120.85,1.341 120.076,16.891
  pour cut-out: 31.661,160.86 31.661,153.66 31.761,153.76 34.261,153.76 34.261,161.26 34.561,161.56
  pour cut-out: 10.561,158.36 13.361,158.36 13.361,155.06 10.561,155.06
  pour cut-out: 10.561,157.86 12.661,157.86 12.661,157.66 10.561,157.66
  pour cut-out: 27.961,158.36 31.661,158.36 31.661,154.46 27.961,154.46
  pour cut-out: 1.281,127.678 40.112,127.678 40.112,1.789 1.545,1.789 1.092,70.785
  pour cut-out: 39.001,45.4 39.612,46.011 120.808,46.011 120.808,8.009 120.657,0.954 114.332,1.534 38.884,1.534
Bottom:
  pour cut-out: 109.079,117.156 109.079,116.292 109.053,116.267 107.529,116.267 107.529,117.258
  pour cut-out: 51.065,56.247 51.065,55.358 52.208,55.358 52.259,55.307 52.589,55.637 52.589,56.45
  pour cut-out: 49.211,57.263 49.998,57.263 50.1,57.364 50.1,58.711 49.008,58.711 48.931,58.634
  pour cut-out: 67.431,82.595 67.433,82.593 79.802,82.593 79.802,75.36 67.434,75.354
  pour cut-out: 1.83,127.678 40.316,127.678 40.316,1.789 1.545,1.789 1.455,15.412
  pour cut-out: 120.492,116.86 158.014,116.86 158.014,1.308 127.319,1.308 120.85,1.341 120.153,15.339
  pour cut-out: 39.001,45.4 39.72,46.119 120.808,46.119 120.808,8.009 120.657,0.954 114.332,1.534 38.884,1.534
  pour cut-out: 120.721,121.69 120.141,121.11 120.121,121.11 120.121,121.93 120.111,121.94 120.621,122.45 120.751,122.45
GND Plane (plane layer: these items are gaps in the copper):
  lines w1: 34.176,160 34.176,155.304 35.521,153.96 37.261,153.96 39.361,156.06 41.811,156.06 44.622,156.06 45.961,154.721 45.961,144.752 47.761,142.952 47.761,135.045 45.8,133.084 45.8,130.474 47.359,128.915 50.415,128.915 54.76,133.26 59.661,133.26 65.261,138.86 76.261,138.86 82.199,132.922 88.07,132.922 88.961,133.813 88.961,147.46 88.861,147.56 90.861,149.56 99.378,149.56 100.678,148.26 105.261,148.26 106.361,149.36 106.361,159.86 106.461,159.96
Power Plane (plane layer: these items are gaps in the copper):
  pour cut-out: 100.921,117.605 100.921,115.965 102.501,115.965 102.456,116.01 102.456,117.665
  lines w0.3: 41.3,132.316 40.815,131.831 40.815,130.61 39.285,129.08 29.485,129.08 28.925,129.64 28.925,134.837 25.811,138.47 25.811,142.57 28.211,144.87 32.811,144.87 34.911,141.67 40.511,141.67 45.211,148.87 45.211,156.17 48.911,156.17 48.911,149.37 52.811,145.47 52.811,133.67 51.111,133.07 44.111,133.07 41.321,132.337 ; 99.852,113.208 99.852,114.551 100.051,114.75 100.051,118.81 99.852,119.009 99.852,120.416 100.112,120.676 100.721,120.676 101.001,120.397 101.001,119.039 100.796,118.835 100.796,114.725 101.001,114.52 101.001,113.132 100.721,112.853 100.213,112.853 99.858,113.208 ; 102.392,113.208 102.392,114.551 102.591,114.75 102.591,118.81 102.392,119.009 102.392,120.416 102.652,120.676 103.261,120.676 103.541,120.397 103.541,119.039 103.336,118.835 103.336,114.725 103.541,114.52 103.541,113.132 103.261,112.853 102.753,112.853 102.398,113.208

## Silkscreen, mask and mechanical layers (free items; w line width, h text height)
Top Overlay:
  lines w0.15: 6.161,128.56 3.561,128.56 3.561,135.06 14.461,135.06 14.461,128.56 11.861,128.56 ; 9.561,137.46 9.561,136.959 31.561,136.96 31.561,137.405 ; 9.561,141.26 9.561,150.66 ; 19.561,128.56 16.261,128.56 16.261,135.06 27.061,135.06 27.061,128.56 23.961,128.56 ; 31.561,141.16 31.561,150.56 ; 32.291,128.56 29.061,128.56 29.061,135.06 39.791,135.06 39.791,128.56 37.791,128.56 ; 128.791,118.34 125.491,118.34 125.491,124.84 136.291,124.84 136.291,118.34 133.191,118.34 ; 148.43,118.36 145.83,118.36 145.83,124.86 156.73,124.86 156.73,118.36 154.13,118.36 ; 34.561,142.22 36.822,142.22 36.822,147.16 34.561,147.16 34.561,142.22 ; 37.081,142.22 37.081,147.16 39.471,147.16 39.471,142.22 37.081,142.22 ; 44.112,54.149 45.125,53.137 52.112,53.137 52.112,58.349 44.112,58.349 44.112,54.149 ; 44.921,114.238 52.121,114.238 52.121,119.414 45.715,119.414 44.921,118.62 44.921,114.238 ; 108.001,114.26 114.261,114.26 114.261,120.56 113.361,121.46 108.001,121.46 108.001,114.26 ; 108.062,52.888 114.289,52.888 115.262,53.861 115.262,58.341 108.062,58.341 108.062,52.888 ; 146.421,155.02 151.211,155.02 151.211,157.281 146.421,157.281 146.421,155.02
  lines w0.3: 47.357,93.89 49.277,93.89 ; 49.882,106.59 51.802,106.59 ; 49.907,68.515 51.827,68.515 ; 49.907,81.215 51.827,81.215 ; 52.091,117.04 52.091,118.96 ; 58.101,82.211 52.802,86.711 58.168,91.448 58.168,82.211 ; 59.752,56.12 59.752,58.04 ; 62.292,117.029 62.292,118.949 ; 72.461,56.15 72.461,58.07 ; 74.992,114.54 74.992,116.46 ; 84.843,109.337 76.347,109.337 80.57,114.309 84.905,109.399 ; 85.161,56.15 85.161,58.07 ; 87.692,114.565 87.692,116.485 ; 97.861,56.15 97.861,58.07 ; 100.366,114.489 100.366,116.409 ; 102.988,82.628 102.988,91.124 107.961,86.9 103.05,82.566 ; 108.302,65.95 110.222,65.95 ; 108.351,78.64 110.271,78.64 ; 108.351,91.34 110.271,91.34 ; 110.886,104.078 112.806,104.078 ; 124.461,131.16 105.861,131.16 105.861,152.26 157.461,152.26 157.561,152.26 157.561,149.46 ; 135.061,131.16 157.561,131.16 157.561,133.96 ; 157.561,139.46 157.561,143.96 ; 75.912,64.1 80.589,58.801 85.089,64.1 75.912,64.1
  text "BL" at 143.295,155.355 h2.5
  text "LCD I2C 16X2" at 124.499,153.577 h2.8
  text "Debug Port" at 107.581,153.1 h2.5
  text "EN3V3" at 1.361,149.96 h2
  text "USB B/C" at 43.211,147.31 h2.8
  text "GND" at 1.261,143.46 h2
  text "LAN" at 98.511,140.41 h2.8
  text "SD" at 84.661,138.56 h2.8
  text "CD" at 84.584,129.503 h2.3 r90
  text "WP" at 87.153,129.474 h2.3 r90
  text "USB A" at 43.411,127.86 h2.8
  text "GND" at 6.621,127.748 h2.5
  text "3V3" at 19.721,127.748 h2.5
  text "5V" at 33.321,127.748 h2.5
  text "DIBP" at 99.833,125.834 h2.3 r90
  text "DIBN" at 92.374,125.783 h2.3 r90
  text "microSD" at 75.161,125.01 h2.8
  text "SDA0" at 115.335,122.378 h2.3
  text "SCL0" at 115.525,119.849 h2.3
  text "GND" at 108.351,119.451 h2.5
  text "PA21" at 54.135,119.185 h2.3 r90
  text "PA20" at 56.705,119.185 h2.3 r90
  text "PA19" at 59.245,119.185 h2.3 r90
  text "PA18" at 61.785,119.185 h2.3 r90
  text "PA17" at 64.225,119.185 h2.3 r90
  text "PA16" at 66.865,119.185 h2.3 r90
  text "PA15" at 69.405,119.185 h2.3 r90
  text "PA14" at 71.895,119.185 h2.3 r90
  text "PA13" at 74.448,119.185 h2.3 r90
  text "PA12" at 76.865,119.185 h2.3 r90
  text "PA11" at 79.405,119.185 h2.3 r90
  text "DTXD" at 81.865,119.185 h2.3 r90
  text "DRXD" at 84.405,119.185 h2.3 r90
  text "PA8" at 86.945,119.185 h2.3 r90
  text "PA7" at 89.485,119.185 h2.3 r90
  text "PA6" at 92.175,119.185 h2.3 r90
  text "PA5" at 94.715,119.185 h2.3 r90
  text "PA4" at 97.255,119.185 h2.3 r90
  text "PA3" at 99.795,119.185 h2.3 r90
  text "PA2" at 102.335,119.185 h2.3 r90
  text "PA1" at 104.875,119.185 h2.3 r90
  text "PA0" at 107.355,119.185 h2.3 r90
  text "3V3" at 128.951,117.528 h2.5
  text "GND" at 148.89,117.548 h2.5
  text "3V3" at 45.68,117.329 h2.5
  text "*" at 57.893,115.524 h4 r90
  text "*" at 60.433,115.524 h4 r90
  text "*" at 62.943,115.524 h4 r90
  text "*" at 65.603,115.524 h4 r90
  text "*" at 67.983,115.524 h4 r90
  text "*" at 70.523,115.524 h4 r90
  text "*" at 83.423,115.424 h4 r90
  text "*" at 85.863,115.424 h4 r90
  text "5" at 62.02,113.811 h3 r90
  text "2" at 54.797,113.034 h3 r90
  text "RX_P" at 112.975,112.128 h2.5
  text "WKUP" at 40.322,112.108 h2.5
  text "10" at 74.503,111.71 h3 r90
  text "15" at 87.457,111.71 h3 r90
  text "2" at 107.336,111.604 h3
  text "20" at 99.903,111.456 h3 r90
  text "GND" at 53.901,111.22 h2
  text "3V3" at 62.401,111.02 h2
  text "*" at 108.895,110.928 h4
  text "S" at 79.591,110.04 h3.9
  text "SHDN" at 40.965,109.578 h2.5
  text "RX_N" at 112.995,109.568 h2.5
  text "*" at 108.895,108.478 h4
  text "NRST" at 41.167,107.038 h2.5
  text "TX_P" at 112.995,107.028 h2.5
  text "*" at 108.895,105.938 h4
  text "*" at 51.477,104.792 h4 r180
  text "VBAT" at 41.003,104.498 h2.5
  text "TX_N" at 112.995,104.488 h2.5
  text "20" at 52.345,104.374 h3
  text "5" at 107.382,104.371 h3
  text "*" at 108.795,103.298 h4
  text "*" at 51.477,102.292 h4 r180
  text "USBA+" at 39.655,101.958 h2.5
  text "3V3Eth" at 112.995,101.948 h2.5
  text "*" at 108.915,100.858 h4
  text "USBA-" at 40.138,99.418 h2.5
  text "EthLD1" at 112.995,99.408 h2.5
  text "*" at 108.895,98.318 h4
  text "*" at 51.577,97.142 h4 r180
  text "GND" at 42.292,96.927 h2.5
  text "EthLD2" at 113.026,96.858 h2.5
  text "*" at 108.865,95.748 h4
  text "*" at 51.567,94.602 h4 r180
  text "USBB+" at 39.655,94.368 h2.5
  text "PA22" at 112.995,94.328 h2.5
  text "10" at 105.512,91.898 h3
  text "USBB-" at 40.138,91.828 h2.5
  text "PA23" at 112.995,91.788 h2.5
  text "15" at 52.121,91.668 h3
  text "*" at 51.477,89.512 h4 r180
  text "GND" at 42.292,89.288 h2.5
  text "PA24" at 112.995,89.248 h2.5
  text "*" at 51.477,86.982 h4 r180
  text "USBC-" at 40.138,86.778 h2.5
  text "PA25" at 112.995,86.708 h2.5
  text "E" at 55.021,85.432 h3.9
  text "W" at 103.4,85.4 h3.6
  text "USBC+" at 39.655,84.208 h2.5
  text "PA26" at 112.995,84.168 h2.5
  text "Aria" at 70.725,82.917 h12
  text "PC31" at 41.982,81.748 h2.5
  text "PA27" at 112.995,81.628 h2.5
  text "PC30" at 41.728,79.208 h2.5
  text "PA28" at 112.995,79.088 h2.5
  text "15" at 105.512,78.944 h3
  text "10" at 52.321,78.914 h3
  text "PC29" at 41.721,76.668 h2.5
  text "PA29" at 112.995,76.548 h2.5
  text "PC28" at 41.717,74.128 h2.5
  text "PA30" at 112.995,74.008 h2.5
  text "PC27" at 41.717,71.588 h2.5
  text "PA31" at 112.995,71.468 h2.5
  text "PC26" at 41.696,69.048 h2.5
  text "ADVref" at 112.995,69.028 h2.5
  text "PC25" at 41.686,66.508 h2.5
  text "20" at 105.258,66.498 h3
  text "PB11" at 112.995,66.388 h2.5
  text "5" at 52.367,66.368 h3
  text "GND" at 102.101,64.92 h2
  text "PC24" at 41.669,63.968 h2.5
  text "PB12" at 112.995,63.848 h2.5
  text "PC23" at 41.713,61.428 h2.5
  text "PB13" at 112.995,61.308 h2.5
  text "3V3" at 94.861,61.16 h2
  text "N" at 79.569,60.921 h3.9
  text "2" at 51.967,59.148 h3
  text "PC22" at 41.73,58.968 h2.5
  text "PB14" at 112.995,58.808 h2.5
  text "15" at 74.503,58.457 h3 r90
  text "10" at 87.303,58.457 h3 r90
  text "5" at 100.003,58.457 h3 r90
  text "20" at 61.903,58.357 h3 r90
  text "2" at 107.423,58.357 h3 r90
  text "GND" at 44.855,53.81 h2.5
  text "3V3" at 110.716,53.726 h2.5
  text "PC1" at 104.973,49.471 h2.5 r90
  text "PC9" at 84.653,49.211 h2.5 r90
  text "PC8" at 87.193,49.207 h2.5 r90
  text "PC7" at 89.733,49.207 h2.5 r90
  text "PC3" at 99.893,49.203 h2.5 r90
  text "PC2" at 102.433,49.219 h2.5 r90
  text "PC0" at 107.413,49.217 h2.5 r90
  text "PC6" at 92.273,49.186 h2.5 r90
  text "PC5" at 94.813,49.175 h2.5 r90
  text "PC4" at 97.353,49.159 h2.5 r90
  text "PC21" at 54.173,48.228 h2.5 r90
  text "PC11" at 79.573,48.228 h2.5 r90
  text "PC20" at 56.813,47.974 h2.5 r90
  text "PC19" at 59.253,47.967 h2.5 r90
  text "PC18" at 61.793,47.963 h2.5 r90
  text "PC17" at 64.333,47.963 h2.5 r90
  text "PC13" at 74.493,47.959 h2.5 r90
  text "PC12" at 77.033,47.976 h2.5 r90
  text "PC10" at 82.113,47.974 h2.5 r90
  text "PC16" at 66.873,47.942 h2.5 r90
  text "PC15" at 69.413,47.932 h2.5 r90
  text "PC14" at 71.953,47.915 h2.5 r90
  text "acmesystems.eu" at 11.285,4.842 h4
  text "BERTA Board for Aria G25 SoM" at 44,2 h6
  text "Made in Italy" at 16.14,1.688 h3
Mechanical 1:
  lines w0.1: 0,1 0,159 ; 0,1.023 ccw(c1.012,1.011) 1,0 159,0 ; 0.001,159 cw(c1.012,158.988) 1.024,160 ; 1,160 159,160 cw(c158.988,158.989) 160,158.977 ; 158.977,0 ccw(c158.989,1.012) 160,1 160,159
Mechanical 3:
  lines w0: 3.8,63.8 156.2,156.2 ; 3.8,156.2 156.2,63.8
  lines w0.05: -0.5,0 0,0 ; 0,-0.5 0,0 ; 0,0.5 0,0 ; 0.5,0 0,0
  text "www.acmesystems.it" at 4.545,200.25 h7.62
  text "BertaBoard Aria G25" at 4.545,186.686 h12.7

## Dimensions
3.8,156.2 to 156.2,156.2 on Mechanical 3
156.2,156.2 to 160,159 on Mechanical 3
3.8,156.2 to 0,159 on Mechanical 3
3.8,156.2 to 1,160 on Mechanical 3
156.2,156.2 to 0,1.023 on Mechanical 3
0,1 to 160,1 on Mechanical 3
1,160 to 1,0 on Mechanical 3
3.8,3.8 to 3.8,156.2 on Mechanical 3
